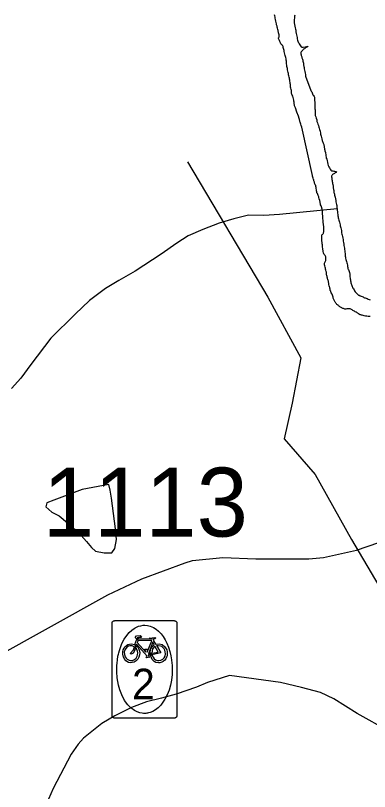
# Model space of a CAD drawing. Extents: x 1662474 to 1856135, y 779280 to 917889.
# Drawn here: x 1728946 to 1730424, y 803442 to 806687 of the extents above; entities that cross this region are included whole.
import ezdxf

# ---------------------------------------------------------------- set-up
doc = ezdxf.new("R2010")
doc.units = 0
for name, color, linetype in [('Cogo Default Point CELL', 7, 'Continuous'), ('Exist Hydrographic Lake Shore', 7, 'Continuous'), ('Exist Hydrographic Misc Water Feature', 7, 'Continuous'), ('Exist Hydrographic Pond Under 1500 Sq Ft', 7, 'Continuous'), ('Exist Road Primary NC Shield Bike CELL', 7, 'Continuous'), ('Exist Road Primary NC Shield Bike NC Label', 7, 'Continuous'), ('Exist Road Secondary Type 51 Attributed', 7, 'Continuous'), ('Exist Utilities Electrical Transmission Line', 7, 'Continuous')]:
    doc.layers.add(name, color=color, linetype=linetype)

msp = doc.modelspace()

# ---------------------------------------------------------------- linework, layer by layer
at = {"layer": 'Exist Hydrographic Lake Shore'}
for points in [[(1730046.1, 806584.9), (1730045.4, 806588.1), (1730044.2, 806590.9), (1730044.2, 806593.3), (1730044.9, 806594.9), (1730046.1, 806597.8), (1730046.6, 806600.9), (1730046.4, 806605.6), (1730045.4, 806610.3), (1730044.2, 806614), (1730043.5, 806616.4), (1730042.8, 806619.2), (1730041.9, 806623.8), (1730040.9, 806628.4), (1730040.1, 806633.2), (1730038.8, 806637.9), (1730037.8, 806642.4), (1730035.9, 806647.1), (1730034.9, 806652.3), (1730033.5, 806657.6), (1730032.8, 806663.6), (1730031.8, 806669.7), (1730030.1, 806674.9), (1730029.4, 806679.9), (1730028.2, 806685.1), (1730027.2, 806690.1)], [(1730111.5, 806688), (1730110.8, 806684.4), (1730110.4, 806681.8), (1730110.4, 806678.6), (1730110.1, 806674.9), (1730109.4, 806670.2), (1730108.9, 806665.8), (1730108.9, 806661.2), (1730108.6, 806658.4), (1730109.4, 806655.2), (1730110.4, 806651.6), (1730111.2, 806647.9), (1730112.2, 806644.4), (1730112.5, 806641.3), (1730112.8, 806637.9), (1730113.4, 806634.5), (1730114.4, 806630), (1730115.6, 806624.8), (1730116.8, 806618.2), (1730118, 806611.6), (1730119.4, 806605.9), (1730120.4, 806600.9), (1730121.8, 806595.1), (1730122.5, 806589.1), (1730123.2, 806583.6), (1730125.1, 806578.9), (1730126.1, 806575.2), (1730128.2, 806571.8), (1730130.4, 806568.1), (1730133.2, 806564.4), (1730135.9, 806559.4), (1730138.8, 806556), (1730141.6, 806554.4), (1730146.6, 806554.7), (1730154.8, 806556), (1730162.6, 806557.1), (1730166.4, 806558.1), (1730165.2, 806555.8), (1730162.4, 806553.9), (1730157.1, 806551.3), (1730151.9, 806547.9), (1730148.8, 806546.1), (1730147.4, 806544.4), (1730145.6, 806542.4), (1730144.2, 806540.2), (1730142.8, 806538.7), (1730141.1, 806537.4), (1730139.2, 806534.8), (1730137.8, 806532.1), (1730137.2, 806529.2), (1730137.8, 806526.4), (1730138.2, 806522.7), (1730139.2, 806519.5), (1730140.1, 806516.6), (1730140.9, 806513.2), (1730141.9, 806510.1), (1730143.2, 806506.9), (1730144, 806503.5), (1730145.4, 806499.9), (1730145.9, 806495.6), (1730146.6, 806491.7), (1730148, 806486.8), (1730148.8, 806480.2), (1730149.8, 806473.6), (1730150.9, 806468.9), (1730151.6, 806464.1), (1730152.4, 806458.1), (1730154, 806452.1), (1730154.8, 806446.1), (1730156.1, 806440), (1730157.1, 806432.4), (1730178.4, 806373.6), (1730179.8, 806370.4), (1730182.4, 806367.1), (1730184.8, 806362.8), (1730186.2, 806359.2), (1730187.4, 806355.5), (1730190, 806351.8), (1730192.4, 806347.9), (1730193.9, 806344.8), (1730194.1, 806341.1), (1730194.4, 806336.3), (1730194.4, 806330.8), (1730195.2, 806323.8), (1730195.8, 806317.7), (1730196, 806312.4), (1730196, 806307.8), (1730196, 806302.5), (1730196.2, 806296.4)], [(1730208.1, 805938.7), (1730206.5, 805942.1), (1730204.6, 805945.8), (1730204.1, 805950), (1730202.9, 805953.7), (1730202, 805958.4), (1730201.2, 805963.1), (1730200.5, 805967.3), (1730200.2, 805971.5), (1730199.1, 805975.2), (1730197.6, 805978.6), (1730196, 805982.2), (1730194.6, 805985.9), (1730193.6, 805990.1), (1730192, 805995.1), (1730190.8, 805999.1), (1730190, 806000.9), (1730188.6, 806006.4), (1730187.6, 806011.1), (1730186.2, 806014.8), (1730185.5, 806018.2), (1730141.1, 806220.3), (1730139.2, 806226.9), (1730137.5, 806231.9), (1730135.6, 806236.3), (1730134, 806240), (1730133.5, 806243.2), (1730133.2, 806246.1), (1730132, 806249.2), (1730130.9, 806252.1), (1730130.1, 806256), (1730126.8, 806265.8), (1730120.6, 806282.8), (1730114.4, 806300.1), (1730111.2, 806308.5), (1730110.8, 806312.7), (1730109.6, 806316.1), (1730108.9, 806319.6), (1730108.9, 806324), (1730108.4, 806327.9), (1730107.5, 806332.9), (1730106.5, 806338.4), (1730104.6, 806344.2), (1730103.4, 806349.7), (1730101.2, 806353.9), (1730099.9, 806357.6), (1730098.6, 806360.5), (1730098.1, 806363.6), (1730098.1, 806367.6), (1730097.6, 806372.6), (1730096.2, 806377.6), (1730095.8, 806383.3), (1730094.6, 806387.2), (1730093.9, 806390.9), (1730093.6, 806395.1), (1730093.4, 806398.8), (1730092.6, 806402.8), (1730092.4, 806406.9), (1730091.2, 806411.9), (1730090.8, 806416.6), (1730090.5, 806420.1), (1730089.8, 806424.2), (1730088.1, 806428.4), (1730087.6, 806433.9), (1730086.2, 806439.2), (1730085.2, 806443.9), (1730083.9, 806448.9), (1730082.9, 806453.6), (1730082.1, 806458.9), (1730080.8, 806464.4), (1730080, 806469.1), (1730079.2, 806474.1), (1730078.4, 806479.4), (1730077.6, 806484.1), (1730077.4, 806488.1), (1730077.4, 806491.7), (1730077.4, 806495.6), (1730076.2, 806500.4), (1730075.2, 806505.9), (1730074, 806510.9), (1730072.9, 806515.1), (1730072.1, 806519.2), (1730070.2, 806524.8), (1730068.8, 806530), (1730067.9, 806535.6), (1730066.9, 806539.8), (1730065.8, 806544.4), (1730065.2, 806548.9), (1730064, 806553.4), (1730062.9, 806557.1), (1730061.9, 806559.2), (1730061.4, 806561.2), (1730059.5, 806562.8), (1730058, 806564.1), (1730056.4, 806565.8), (1730054.2, 806568.4), (1730052.1, 806572.8), (1730050.1, 806578.1), (1730047.8, 806581.8), (1730046.1, 806584.9)], [(1730196.2, 806296.4), (1730196.8, 806291.7), (1730196.8, 806286.2), (1730196.8, 806279.9), (1730197, 806273.6), (1730197.2, 806269.1), (1730198.4, 806266), (1730199.6, 806262.3), (1730201.2, 806257.6), (1730203.4, 806250.5), (1730204.6, 806243.9), (1730206.8, 806237.9), (1730208.4, 806232.4), (1730210.4, 806226.1), (1730212.5, 806220.1), (1730214.1, 806215.6), (1730215.6, 806210.4), (1730217.2, 806203.2), (1730218.9, 806195.4), (1730219.9, 806190.1), (1730221.2, 806185.9), (1730222.2, 806182), (1730223.2, 806177.2), (1730224.9, 806170.7), (1730226.8, 806163.6), (1730228, 806159.7), (1730229.4, 806156.8), (1730230.4, 806153.1), (1730232.5, 806146.8), (1730234.2, 806137.1), (1730236.4, 806127.9), (1730238, 806123.2), (1730237.8, 806121.1), (1730238.8, 806116.9), (1730239.5, 806114.8), (1730240.4, 806111.1), (1730240.9, 806105.6), (1730241.1, 806100.4), (1730242.5, 806094.9), (1730243.5, 806090.1), (1730245.4, 806085.7), (1730246.6, 806079.9), (1730248.8, 806072.3), (1730250.4, 806065.2), (1730251.4, 806060.2), (1730252.6, 806056.8), (1730254.2, 806053.7), (1730256.4, 806050), (1730259.5, 806044.8), (1730262.1, 806040), (1730265, 806037.9), (1730267.4, 806036.6), (1730270.8, 806037.1), (1730274.5, 806036.3), (1730277.4, 806036.3), (1730280.5, 806034.5), (1730282.4, 806034), (1730285.8, 806034.2), (1730283.1, 806030.3), (1730280.8, 806028.4), (1730278.4, 806026.6), (1730275.2, 806025.1), (1730272.4, 806023.2), (1730270, 806021.6), (1730267.9, 806019.6), (1730266.9, 806017.7), (1730265.5, 806014.8), (1730265.5, 806011.7), (1730266.1, 806008.2), (1730266.9, 806005.1), (1730267.1, 806000.9), (1730267.6, 805996.2), (1730268.4, 805992.2), (1730269.2, 805989.1), (1730269.8, 805984.9), (1730270.2, 805979.4), (1730271.6, 805972.8), (1730272.6, 805966.2), (1730274, 805959.7), (1730274.5, 805955), (1730274.8, 805951.6), (1730275.5, 805947.1), (1730276, 805943.2), (1730277.4, 805939.8), (1730278.4, 805934.8), (1730280, 805927.7), (1730281.5, 805920.3), (1730282.9, 805913.5), (1730283.9, 805908), (1730285.2, 805902.5), (1730286.2, 805896.7), (1730287.4, 805892), (1730287.6, 805887.2), (1730288.1, 805882.8), (1730288.6, 805878.1), (1730289.1, 805872.3), (1730290, 805866), (1730290.8, 805859.9), (1730291.8, 805854.4), (1730292, 805849.4)], [(1730256.6, 805552.9), (1730256.1, 805556.1), (1730254.5, 805561.8), (1730254, 805563.9), (1730253.8, 805567.3), (1730253.2, 805570.2), (1730252.6, 805572.6), (1730252.4, 805575.7), (1730251.6, 805578.9), (1730250.4, 805582.2), (1730249.2, 805585.7), (1730248.2, 805588.8), (1730247.8, 805592.2), (1730246.6, 805595.7), (1730245.6, 805599.1), (1730244.8, 805602.5), (1730244, 805606.2), (1730244, 805610.4), (1730244, 805613.2), (1730243.2, 805616.9), (1730241.6, 805621.6), (1730240.1, 805626.4), (1730239.5, 805630.3), (1730238.8, 805634.8), (1730238, 805639.5), (1730235.9, 805644.5), (1730235.6, 805647.4), (1730236.4, 805650.8), (1730238, 805654.4), (1730240.1, 805659.2), (1730241.1, 805662.3), (1730241.9, 805666), (1730241.9, 805669.7), (1730241.6, 805673.6), (1730240.9, 805677.6), (1730240.1, 805680.4), (1730238.2, 805683.6), (1730236.6, 805685.7), (1730234.9, 805687.5), (1730233.2, 805689.6), (1730232, 805694.9), (1730230.6, 805700.4), (1730230.4, 805703.6), (1730229.6, 805707.5), (1730229.4, 805712.2), (1730228.2, 805717.7), (1730228, 805721.9), (1730227.8, 805724.8), (1730227.2, 805728.5), (1730226.8, 805731.9), (1730226.5, 805735.6), (1730225.6, 805739.2), (1730225.1, 805742.1), (1730224.4, 805746.3), (1730224.4, 805751.3), (1730224.4, 805755.8), (1730224.9, 805759.4), (1730224.9, 805762.3), (1730224.4, 805766), (1730224.4, 805768.4), (1730226.5, 805770.4), (1730228.8, 805772.8), (1730230.6, 805774.7), (1730232, 805776), (1730232.2, 805779.6), (1730232.5, 805782.2), (1730232.8, 805784.1), (1730233.5, 805787), (1730233.5, 805789.4), (1730233.8, 805794.9), (1730233.2, 805803), (1730232, 805812.8), (1730230.6, 805821.9), (1730230.4, 805826.9), (1730230.1, 805830.3), (1730229.6, 805836.1), (1730229.6, 805841.6), (1730229.4, 805844.8), (1730228.8, 805848.4), (1730228.2, 805855.5), (1730228, 805861.6), (1730227.8, 805865.2), (1730227.2, 805868.6), (1730226.5, 805873.4), (1730225.6, 805878.1), (1730224.9, 805880.4), (1730224.4, 805883.1), (1730223.2, 805887), (1730221.8, 805891.2), (1730219.9, 805895.4), (1730219.4, 805898.8), (1730218.2, 805901.9), (1730217.2, 805906.4), (1730216, 805913.5), (1730213.6, 805920.1), (1730212.2, 805925.3), (1730211.8, 805928.8), (1730210.8, 805931.6), (1730209.4, 805934.5), (1730208.1, 805938.7)], [(1730292, 805849.4), (1730292.9, 805844.5), (1730293.6, 805841.1), (1730294.4, 805836.3), (1730295.8, 805831.1), (1730297.2, 805826.4), (1730298.4, 805821.9), (1730299.6, 805817.7), (1730300.8, 805811.7), (1730302, 805806.7), (1730302.9, 805802.8), (1730304.4, 805798.3), (1730305.5, 805793.6), (1730306.5, 805788.1), (1730306.8, 805783.1), (1730307.5, 805777.6), (1730308.4, 805772.8), (1730309.6, 805767.6), (1730310.8, 805762.1), (1730312, 805756), (1730313.6, 805749.8), (1730314.6, 805743.7), (1730315.6, 805737.6), (1730316.5, 805731.1), (1730317.2, 805724.6), (1730317.8, 805718.8), (1730318.9, 805713.2), (1730319.6, 805707.8), (1730320.4, 805702.8), (1730320.6, 805697.2), (1730321.8, 805691.8), (1730322, 805685.9), (1730322.5, 805680.9), (1730323.5, 805676.2), (1730324.1, 805671.5), (1730325.1, 805666.2), (1730326.4, 805662.3), (1730328, 805658.4), (1730329.9, 805653.1), (1730330.6, 805648.1), (1730332, 805642.9), (1730332.5, 805637.9), (1730332.8, 805632.4), (1730334, 805627.9), (1730335.9, 805624), (1730338, 805620.3), (1730339.5, 805616.4), (1730340.4, 805611.7), (1730341.1, 805605.6), (1730341.6, 805600.1), (1730341.9, 805594.4), (1730342.5, 805588.8), (1730343.2, 805585.4), (1730344.2, 805581.2), (1730344.8, 805577.3), (1730345.4, 805572.8), (1730346.4, 805568.6), (1730347.4, 805564.4), (1730348.2, 805562.1), (1730349.5, 805557.6), (1730351.4, 805553.9), (1730353, 805550.5), (1730354.8, 805547.1), (1730356.6, 805543.4), (1730359.2, 805539.2), (1730361.9, 805535.6), (1730364.5, 805531.9), (1730366.9, 805528.8), (1730369.8, 805525.9), (1730372.4, 805522.4), (1730375.2, 805520.3), (1730378.4, 805518), (1730381.2, 805516.9), (1730383.9, 805515.1), (1730386.8, 805514.1), (1730389.8, 805512.8), (1730393.4, 805511.4), (1730396.8, 805510.1), (1730399.9, 805508.2), (1730402.5, 805506.9), (1730405.8, 805505.6), (1730409.6, 805504.3), (1730414.1, 805502.8), (1730418.9, 805501.2), (1730423.2, 805499.1), (1730427.2, 805497.2)], [(1730426.8, 805427.7), (1730422.5, 805428.5), (1730418, 805428.5), (1730412.8, 805429), (1730407.5, 805429.2), (1730402, 805430.8), (1730397.2, 805432.4), (1730393.4, 805433.8), (1730390, 805434.2), (1730387.4, 805435.1), (1730384.5, 805435.6), (1730381.5, 805436.9), (1730378.6, 805439.5), (1730375.2, 805441.6), (1730372.6, 805443.7), (1730370.2, 805445.6), (1730367.9, 805446.3), (1730364, 805447.9), (1730360.9, 805449.8), (1730357.1, 805451.3), (1730353.8, 805453.9), (1730351.4, 805455.8), (1730348.8, 805456.8), (1730345.6, 805459.4), (1730342.8, 805460.8), (1730339.5, 805460.8), (1730337.2, 805460.2), (1730335.4, 805459.7), (1730331.6, 805459.7), (1730328.8, 805460), (1730324.9, 805459.2), (1730321.1, 805459.2), (1730317.8, 805460), (1730315.1, 805461.6), (1730312.8, 805462.1), (1730310.4, 805463.4), (1730308.1, 805464.4), (1730305.8, 805466), (1730302.9, 805467.1), (1730300.5, 805468.9), (1730297.6, 805471.5), (1730294.6, 805473.4), (1730292.4, 805475.2), (1730290.5, 805476.5), (1730288.1, 805478.9), (1730285.8, 805481.5), (1730283.6, 805483.3), (1730282.4, 805486.2), (1730281, 805488.1), (1730279.2, 805490.9), (1730277.6, 805493.6), (1730276.2, 805496.4), (1730275.2, 805498.8), (1730274, 805501.9), (1730272.6, 805504.9), (1730271.6, 805508.8), (1730270.2, 805512.8), (1730268.8, 805517.2), (1730267.4, 805521.9), (1730264.2, 805527.7), (1730261.9, 805533.8), (1730260.2, 805537.4), (1730259.5, 805539.2), (1730259, 805542.4), (1730258.8, 805546.1), (1730257.6, 805550), (1730256.6, 805552.9)]]:
    msp.add_lwpolyline(points, dxfattribs=at)
at = {"layer": 'Exist Hydrographic Misc Water Feature'}
for points in [[(1730288.2, 805878.6), (1730048.2, 805854.3), (1729982.2, 805850.9), (1729918, 805851.5), (1729857.9, 805836), (1729795.8, 805818.7), (1729727.5, 805791.3), (1729667.2, 805765.8), (1729618.8, 805734.3), (1729554.4, 805688.9), (1729445.8, 805617.9), (1729377.3, 805578.5), (1729320.9, 805545), (1729254.5, 805495.6), (1729194, 805438.2), (1729093.1, 805337.1), (1729009.8, 805227.9), (1728967.4, 805170.3), (1728928.8, 805126.6)], [(1730507.7, 803693.3), (1730372.6, 803768.5), (1730275, 803829.4), (1730219.2, 803856), (1730139.5, 803876.8), (1730051.7, 803897.7), (1729839.9, 803927.7), (1729747.4, 803898.4), (1729701.5, 803878.9), (1729617, 803849.7), (1729554.9, 803832.3), (1729492.5, 803816.9), (1729430.4, 803793.5), (1729360.1, 803758.1), (1729305.7, 803726.7), (1729229, 803665.3), (1729206.9, 803639.5), (1729178.4, 803597.8), (1729103.1, 803454.5), (1729082.8, 803410.6)]]:
    msp.add_lwpolyline(points, dxfattribs=at)
at = {"layer": 'Exist Hydrographic Pond Under 1500 Sq Ft'}
msp.add_lwpolyline([(1729334.7, 804726.4), (1729224.6, 804705.5), (1729106.1, 804660.5), (1729076, 804648.8), (1729071.9, 804632.8), (1729097.7, 804610.6), (1729127.4, 804594.3), (1729163.3, 804565.9), (1729209, 804525.5), (1729242.7, 804487.2), (1729262.4, 804463), (1729280.2, 804446.8), (1729316.1, 804440.5), (1729348.1, 804440.1), (1729360.4, 804458.1), (1729366.7, 804496), (1729363, 804540.1), (1729346.4, 804668.2), (1729340.5, 804702.3), (1729334.7, 804726.4)], dxfattribs=at)
at = {"layer": 'Exist Road Primary NC Shield Bike CELL'}
for points in [[(1729358.6, 804156.4), (1729359.4, 804156.5), (1729392.5, 804156.5), (1729575.8, 804156.5), (1729608.9, 804156.5), (1729610, 804156.4), (1729610.7, 804156.3), (1729611.4, 804156.1), (1729612.2, 804155.9), (1729612.9, 804155.6), (1729614.2, 804155), (1729614.8, 804154.6), (1729615.4, 804154.1), (1729616.2, 804153.5), (1729617.1, 804152.5), (1729617.7, 804151.7), (1729618, 804151.3), (1729618.2, 804150.9), (1729618.5, 804150.4), (1729618.7, 804150), (1729618.9, 804149.5), (1729619.1, 804148.8), (1729619.4, 804147.8), (1729619.5, 804146.9), (1729619.5, 804146.6), (1729619.6, 804146.2), (1729619.6, 804112.7), (1729619.6, 803792.8), (1729619.6, 803759.8), (1729619.5, 803758.6), (1729619.4, 803757.9), (1729619.2, 803757.2), (1729619, 803756.4), (1729618.8, 803755.7), (1729618.1, 803754.4), (1729617.7, 803753.8), (1729617.3, 803753.2), (1729616.7, 803752.5), (1729616.2, 803752), (1729615.6, 803751.5), (1729615.3, 803751.3), (1729614.8, 803750.9), (1729614.4, 803750.6), (1729614, 803750.4), (1729613.5, 803750.2), (1729612.6, 803749.8), (1729611.9, 803749.5), (1729611, 803749.3), (1729610.5, 803749.2), (1729610.1, 803749.1), (1729609.7, 803749.1), (1729609.3, 803749), (1729608.8, 803749), (1729575.8, 803749), (1729392.5, 803749), (1729359.5, 803749), (1729358.8, 803749.1), (1729358.3, 803749.1), (1729357.6, 803749.2), (1729356.9, 803749.4), (1729356.2, 803749.6), (1729355.5, 803749.8), (1729354.7, 803750.2), (1729354.1, 803750.5), (1729353.5, 803750.9), (1729352.9, 803751.3), (1729352.6, 803751.6), (1729352.2, 803751.9), (1729351.9, 803752.2), (1729351.5, 803752.7), (1729351.1, 803753.1), (1729350.8, 803753.5), (1729350.5, 803754), (1729350.2, 803754.4), (1729349.9, 803754.9), (1729349.7, 803755.5), (1729349.5, 803756), (1729349.4, 803756.3), (1729349.2, 803756.6), (1729349.2, 803756.8), (1729349.1, 803757), (1729349.1, 803757.3), (1729349, 803757.5), (1729348.9, 803757.8), (1729348.9, 803758), (1729348.9, 803758.3), (1729348.8, 803758.5), (1729348.8, 803758.7), (1729348.8, 803759), (1729348.7, 803759.6), (1729348.7, 803792.8), (1729348.7, 804112.7), (1729348.7, 804145.7), (1729348.8, 804146.9), (1729348.9, 804147.6), (1729349.1, 804148.3), (1729349.3, 804149), (1729349.6, 804149.7), (1729350.2, 804151.1), (1729350.6, 804151.7), (1729351, 804152.3), (1729351.7, 804153), (1729352.7, 804154), (1729353.5, 804154.6), (1729353.9, 804154.9), (1729354.3, 804155.1), (1729354.8, 804155.3), (1729355.2, 804155.5), (1729355.7, 804155.7), (1729356.4, 804156), (1729357.4, 804156.2), (1729358.2, 804156.4)], [(1729484.1, 803768.5), (1729479.5, 803768.7), (1729475.1, 803769.1), (1729465.1, 803770.8), (1729453.9, 803774.9), (1729447.4, 803778.1), (1729442, 803781.1), (1729436.4, 803785), (1729428.4, 803790.9), (1729414.7, 803804.7), (1729401.2, 803822.8), (1729389.3, 803845.9), (1729381.1, 803866.7), (1729375.8, 803887.2), (1729370.2, 803918.1), (1729368.3, 803942.4), (1729368.2, 803954.3), (1729368.4, 803963), (1729368.7, 803969.2), (1729369.4, 803978.5), (1729370.8, 803992.8), (1729373.4, 804007.4), (1729375.4, 804016.8), (1729376.8, 804022.1), (1729379.5, 804031.7), (1729382, 804040.2), (1729389.9, 804060.7), (1729399.7, 804079.2), (1729410.5, 804094.9), (1729420.1, 804106.6), (1729431.5, 804117.4), (1729440.5, 804123.3), (1729445.1, 804126.1), (1729450.3, 804128.9), (1729458.9, 804132.8), (1729469.3, 804135.5), (1729478.6, 804137), (1729486.3, 804137.2), (1729497.2, 804136), (1729508.6, 804132.9), (1729521.6, 804127.3), (1729532.8, 804120.4), (1729542.6, 804112.1), (1729553.3, 804101.1), (1729562, 804089.7), (1729570.5, 804075.8), (1729577.7, 804062.2), (1729584.8, 804045), (1729590.4, 804026.9), (1729594.4, 804009.9), (1729597.4, 803993.3), (1729598.9, 803978.7), (1729599.4, 803970.6), (1729600.4, 803951.6), (1729599.5, 803931.3), (1729596.7, 803907.7), (1729592.5, 803887), (1729586.7, 803866.1), (1729578.8, 803845.9), (1729569.7, 803828.4), (1729561.2, 803815.3), (1729552.3, 803803.8), (1729541.1, 803792.1), (1729530.8, 803783.8), (1729519.5, 803777.3), (1729508.1, 803772.4), (1729501, 803770.5), (1729496.8, 803769.8), (1729493.4, 803769.1), (1729489.5, 803768.8)], [(1729503.6, 804083.2), (1729527.7, 804086.1), (1729529.5, 804084.3), (1729528.1, 804080.5), (1729522.1, 804078.7), (1729520.6, 804075.4), (1729530.7, 804058.3), (1729545.2, 804059), (1729558, 804056.1), (1729569.3, 804047.6), (1729574.6, 804039), (1729577.2, 804034.4), (1729579, 804026.6), (1729579.4, 804018.4), (1729578.4, 804009.9), (1729576.6, 804003.4), (1729572.9, 803996.5), (1729569.4, 803991.3), (1729562.7, 803985.9), (1729556.6, 803982.3), (1729548.2, 803980.3), (1729542.9, 803980), (1729532.1, 803981.7), (1729525.2, 803985.2), (1729521.9, 803988), (1729516.7, 803994.5), (1729513.3, 804000.6), (1729508.7, 804012.8), (1729507.6, 804018.7), (1729515, 804013.4), (1729520.8, 804003.5), (1729525, 803996.8), (1729530.3, 803993), (1729538.5, 803989.7), (1729544.5, 803989.5), (1729552.7, 803991.3), (1729560.2, 803995.6), (1729565.7, 804000.9), (1729569.9, 804008.1), (1729571.4, 804018.1), (1729571.1, 804026.3), (1729569.3, 804033), (1729565.8, 804039.1), (1729562.2, 804043.4), (1729556.2, 804047.9), (1729550.5, 804049.7), (1729541.2, 804051.5), (1729534.7, 804052.2), (1729552.2, 804022.6), (1729515, 804013.4), (1729507.6, 804018.7), (1729541.8, 804024.8), (1729527.6, 804049.3), (1729517.7, 804038.7), (1729514.9, 804020.2), (1729507.6, 804018.7), (1729508, 804026.5), (1729511.1, 804038.3), (1729516.6, 804046.5), (1729524.3, 804055.4), (1729519.4, 804065.9), (1729500.6, 804018), (1729507.7, 804018.8), (1729508.7, 804012.8), (1729500.2, 804011.8), (1729502, 804006.6), (1729507.1, 804003.9), (1729494.5, 804001.1), (1729491.4, 804005), (1729496, 804007.4), (1729451.3, 804058.5), (1729449.6, 804053.6), (1729455.8, 804045.3), (1729459.9, 804037.3), (1729462.7, 804028.7), (1729464.1, 804021.3), (1729463.3, 804013.8), (1729461.2, 804003.9), (1729456.3, 803995), (1729449.4, 803988.2), (1729441.7, 803983.4), (1729432.1, 803981.1), (1729425.1, 803980.5), (1729418, 803981.4), (1729405.6, 803988.9), (1729401.6, 803993.5), (1729395.9, 804003.8), (1729393.5, 804016.8), (1729393.3, 804026), (1729395.7, 804034.2), (1729399.3, 804041.5), (1729403.4, 804046.8), (1729409.5, 804052.8), (1729414.8, 804056.1), (1729421.7, 804058.2), (1729428.7, 804058.9), (1729444, 804057.2), (1729447.5, 804048.9), (1729442.8, 804030), (1729436.7, 804020), (1729427.9, 804015.9), (1729424.4, 804019.4), (1729438.7, 804033.9), (1729441.8, 804047.6), (1729438.6, 804049.1), (1729432.6, 804051), (1729423, 804051.3), (1729417.6, 804049.6), (1729410.1, 804045.3), (1729403.1, 804036), (1729399.9, 804026.3), (1729401.2, 804015.6), (1729404, 804005.7), (1729407.5, 803999.2), (1729412.5, 803995.3), (1729419.8, 803990.8), (1729426.2, 803989.7), (1729434.3, 803990.2), (1729442.1, 803993.5), (1729448.8, 804000.3), (1729453.1, 804008.4), (1729455.5, 804014.2), (1729456.2, 804021.6), (1729455.1, 804029.5), (1729451.4, 804038.6), (1729444, 804057.2), (1729451.6, 804078.9), (1729457.1, 804073.2), (1729454.1, 804064.7), (1729489.7, 804024.8), (1729488.7, 804029.9), (1729484.9, 804036.2), (1729486.6, 804037.7), (1729496.9, 804037.7), (1729494.9, 804030.3), (1729496, 804025.2), (1729514.9, 804072.8), (1729457.1, 804073.2), (1729451.6, 804078.9), (1729445, 804086), (1729450.7, 804092.7), (1729466, 804094.7), (1729472.1, 804089.9), (1729468.9, 804085.6), (1729459.5, 804086.6), (1729453.2, 804085.2), (1729454.6, 804083.9), (1729457.9, 804083.9), (1729456.4, 804080.7), (1729515.7, 804080.2), (1729516, 804081.6)]]:
    msp.add_lwpolyline(points, close=True, dxfattribs=at)
at = {"layer": 'Exist Road Secondary Type 51 Attributed'}
msp.add_lwpolyline([(1728364.1, 803727.1), (1729331.1, 804264.3), (1729472.9, 804330.7), (1729654.1, 804397.8), (1729684.3, 804407.8), (1729811.7, 804421.2), (1729949.2, 804414.5), (1730170.6, 804414.5), (1730231.7, 804421.2), (1730369.5, 804450.9), (1730559.9, 804516.9), (1730827.4, 804627.6), (1731052.2, 804722.3), (1731215.7, 804789.7), (1731346, 804847.3), (1731400, 804879.9), (1731431.7, 804898.4), (1731506.2, 804952.7), (1731566.3, 805009.2), (1731783, 805270.7)], dxfattribs=at)
at = {"layer": 'Exist Utilities Electrical Transmission Line'}
msp.add_lwpolyline([(1729663.4, 806075.3), (1729999.5, 805509.1), (1730137.7, 805255.6), (1730101.1, 805066.3), (1730067.2, 804916.6), (1730197, 804766.9), (1730349.1, 804495.3), (1730544.5, 804162.8), (1730583.4, 804090.5), (1730529.6, 803381.9), (1730486.5, 803004.7)], dxfattribs=at)

# ---------------------------------------------------------------- texts
at = {"layer": 'Cogo Default Point CELL'}
msp.add_text('1113', height=288, dxfattribs=at).set_placement((1729059.4, 804508.2))
at = {"layer": 'Exist Road Primary NC Shield Bike NC Label'}
msp.add_text('2', height=127.5, dxfattribs=at).set_placement((1729432.4, 803828.1))

doc.saveas('drawing.dxf')
